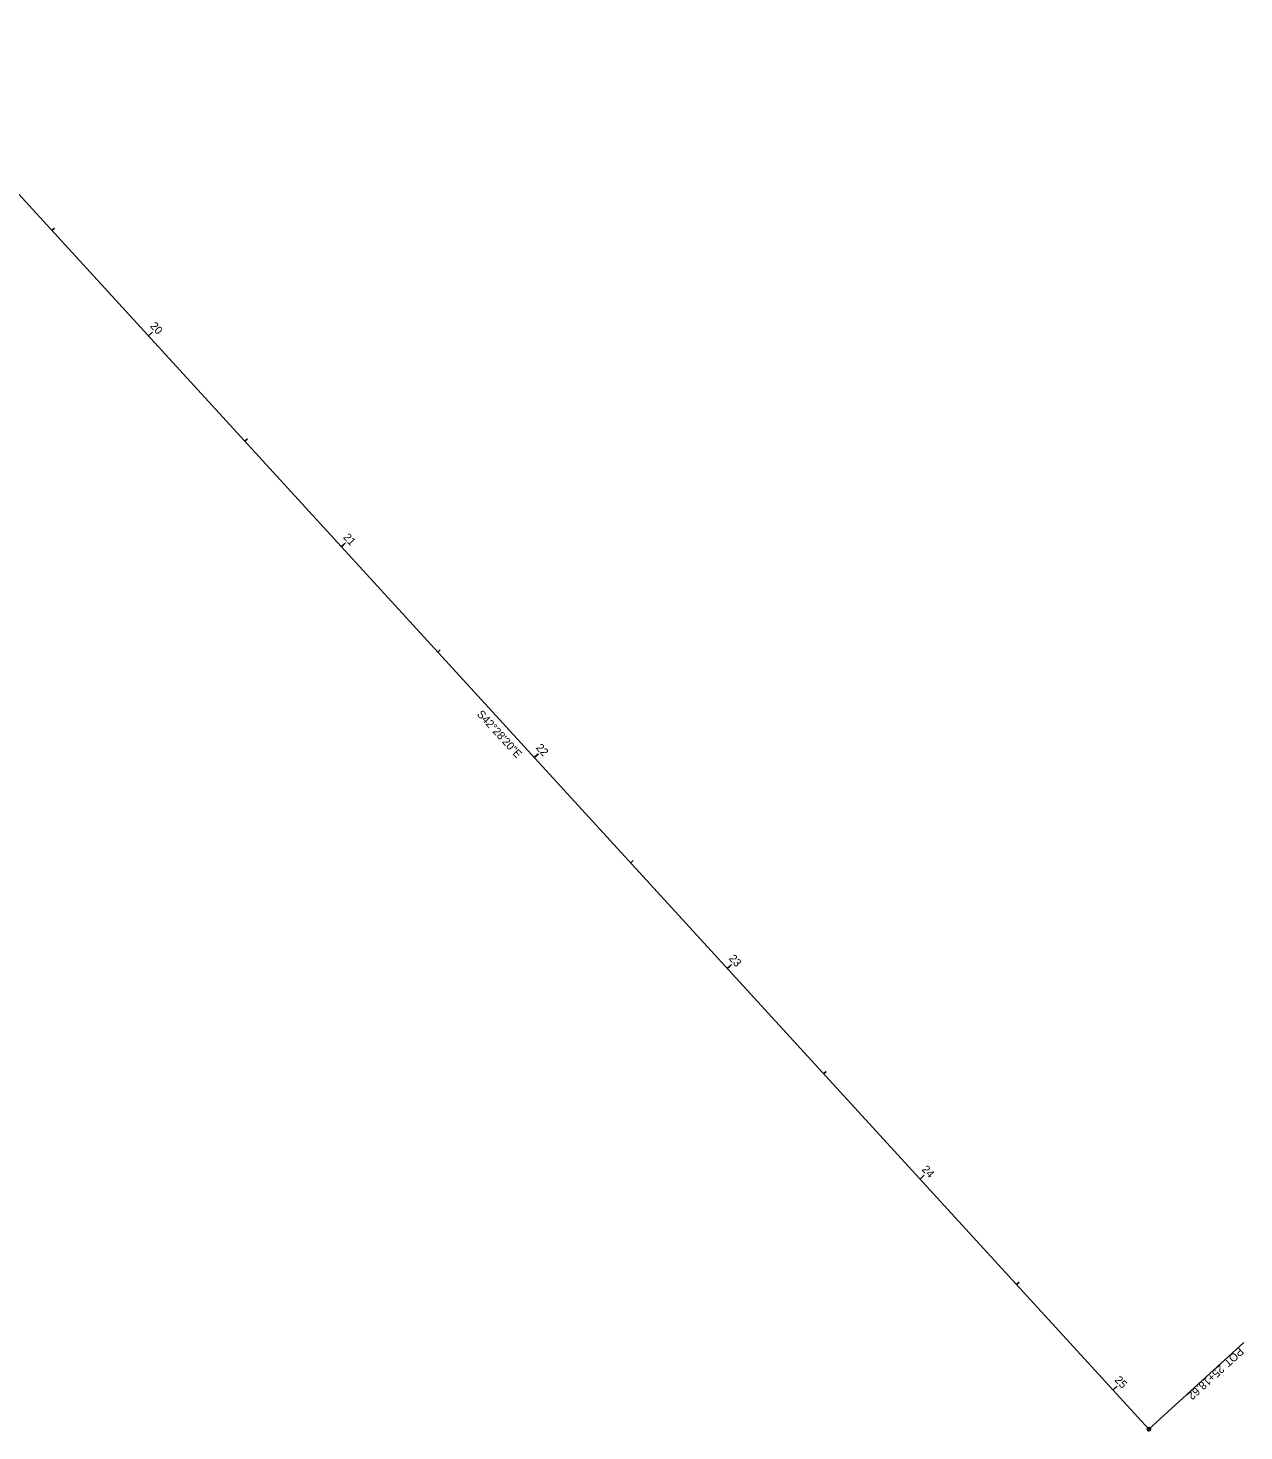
# Model space of a CAD drawing. Extents: x 2196614 to 2198263, y 660890 to 662319.
# Drawn here: x 2197837.9 to 2198263.4, y 660890.5 to 661381.3 of the extents above; entities that cross this region are included whole.
import ezdxf

# ---------------------------------------------------------------- set-up
doc = ezdxf.new("R2010")
doc.units = 0
for name, color, linetype in [('Default', 7, 'Continuous'), ('GE_X_Alignment', 7, 'Continuous'), ('GE_X_Alignment_1000_Stations', 7, 'Continuous'), ('GE_X_Alignment_100_Stations', 7, 'Continuous'), ('GE_X_Alignment_500_Stations', 7, 'Continuous')]:
    doc.layers.add(name, color=color, linetype=linetype)

msp = doc.modelspace()

# ---------------------------------------------------------------- linework, layer by layer
at = {"layer": 'Default'}
for centre in [(2197879.99, 661273.63), (2197879.99, 661273.63), (2197879.99, 661273.63), (2197947.51, 661199.87), (2198005.78, 661136.22), (2198005.78, 661136.22), (2198005.78, 661136.22), (2198005.78, 661136.22), (2198005.78, 661136.22), (2198005.78, 661136.22), (2198015.04, 661126.11), (2198082.56, 661052.35), (2198150.08, 660978.59), (2198217.61, 660904.83), (2198217.61, 660904.83), (2198230.18, 660891.09), (2198230.18, 660891.09), (2198230.18, 660891.09)]:
    msp.add_circle(centre, 0.0000833, dxfattribs=at)
at = {"layer": 'GE_X_Alignment'}
msp.add_line((2197781.39, 661381.34), (2198230.18, 660891.09), dxfattribs=at)
at = {"layer": 'GE_X_Alignment_1000_Stations'}
for p, q in [((2197879.99, 661273.63), (2197881.47, 661274.98)), ((2198230.18, 660891.09), (2198263.37, 660921.48)), ((2198217.61, 660904.83), (2198218.49, 660905.64))]:
    msp.add_line(p, q, dxfattribs=at)
msp.add_circle((2198230.18, 660891.09), 0.6, dxfattribs=at)
at = {"layer": 'GE_X_Alignment_100_Stations'}
for p, q in [((2197846.23, 661310.51), (2197847.11, 661311.32)), ((2197879.99, 661273.63), (2197881.47, 661274.98)), ((2197913.75, 661236.75), (2197914.64, 661237.56)), ((2197947.51, 661199.87), (2197948.99, 661201.22)), ((2197981.28, 661162.99), (2197982.16, 661163.8)), ((2198015.04, 661126.11), (2198016.51, 661127.46)), ((2198048.8, 661089.23), (2198049.68, 661090.04)), ((2198082.56, 661052.35), (2198084.04, 661053.7)), ((2198116.32, 661015.47), (2198117.21, 661016.28)), ((2198150.08, 660978.59), (2198151.56, 660979.94)), ((2198183.85, 660941.71), (2198184.73, 660942.52)), ((2198230.18, 660891.09), (2198263.37, 660921.48)), ((2198217.61, 660904.83), (2198219.08, 660906.18))]:
    msp.add_line(p, q, dxfattribs=at)
msp.add_circle((2198230.18, 660891.09), 0.6, dxfattribs=at)
at = {"layer": 'GE_X_Alignment_500_Stations'}
for p, q in [((2197879.99, 661273.63), (2197881.47, 661274.98)), ((2197947.51, 661199.87), (2197948.4, 661200.68)), ((2198015.04, 661126.11), (2198015.92, 661126.92)), ((2198082.56, 661052.35), (2198083.45, 661053.16)), ((2198150.08, 660978.59), (2198150.97, 660979.4)), ((2198230.18, 660891.09), (2198263.37, 660921.48)), ((2198217.61, 660904.83), (2198219.08, 660906.18))]:
    msp.add_line(p, q, dxfattribs=at)
msp.add_circle((2198230.18, 660891.09), 0.6, dxfattribs=at)

# ---------------------------------------------------------------- texts
at = {"layer": 'GE_X_Alignment_1000_Stations'}
for s, rotation, p in [('20', 312.4723, (2197880.39, 661276.97)), ('S42°28\'20"E', 312.4723, (2197994.77, 661141.14)), ('POT', 222.4723, (2198261.77, 660919.95)), ('25+18.62', 222.4723, (2198255.04, 660913.78))]:
    msp.add_text(s, height=2.8, rotation=rotation, dxfattribs=at).set_placement(p)
at = {"layer": 'GE_X_Alignment_100_Stations'}
for s, rotation, p in [('20', 312.4723, (2197880.39, 661276.97)), ('21', 312.4723, (2197947.99, 661203.05)), ('S42°28\'20"E', 312.4723, (2197994.77, 661141.14)), ('22', 312.4723, (2198015.41, 661129.41)), ('23', 312.4723, (2198082.97, 661055.67)), ('24', 312.4723, (2198150.48, 660981.86)), ('POT', 222.4723, (2198261.77, 660919.95)), ('25', 312.4723, (2198218, 660908.18)), ('25+18.62', 222.4723, (2198255.04, 660913.78))]:
    msp.add_text(s, height=2.8, rotation=rotation, dxfattribs=at).set_placement(p)
at = {"layer": 'GE_X_Alignment_500_Stations'}
for s, rotation, p in [('20', 312.4723, (2197880.39, 661276.97)), ('S42°28\'20"E', 312.4723, (2197994.77, 661141.14)), ('POT', 222.4723, (2198261.77, 660919.95)), ('25', 312.4723, (2198218, 660908.18)), ('25+18.62', 222.4723, (2198255.04, 660913.78))]:
    msp.add_text(s, height=2.8, rotation=rotation, dxfattribs=at).set_placement(p)

doc.saveas('drawing.dxf')
